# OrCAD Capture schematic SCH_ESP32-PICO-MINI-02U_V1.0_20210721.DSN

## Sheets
1 01_DesignBlock: title: <ESP32-PICO-MINI-02U>; rev: V1.0; note: <01_DesignBlock>
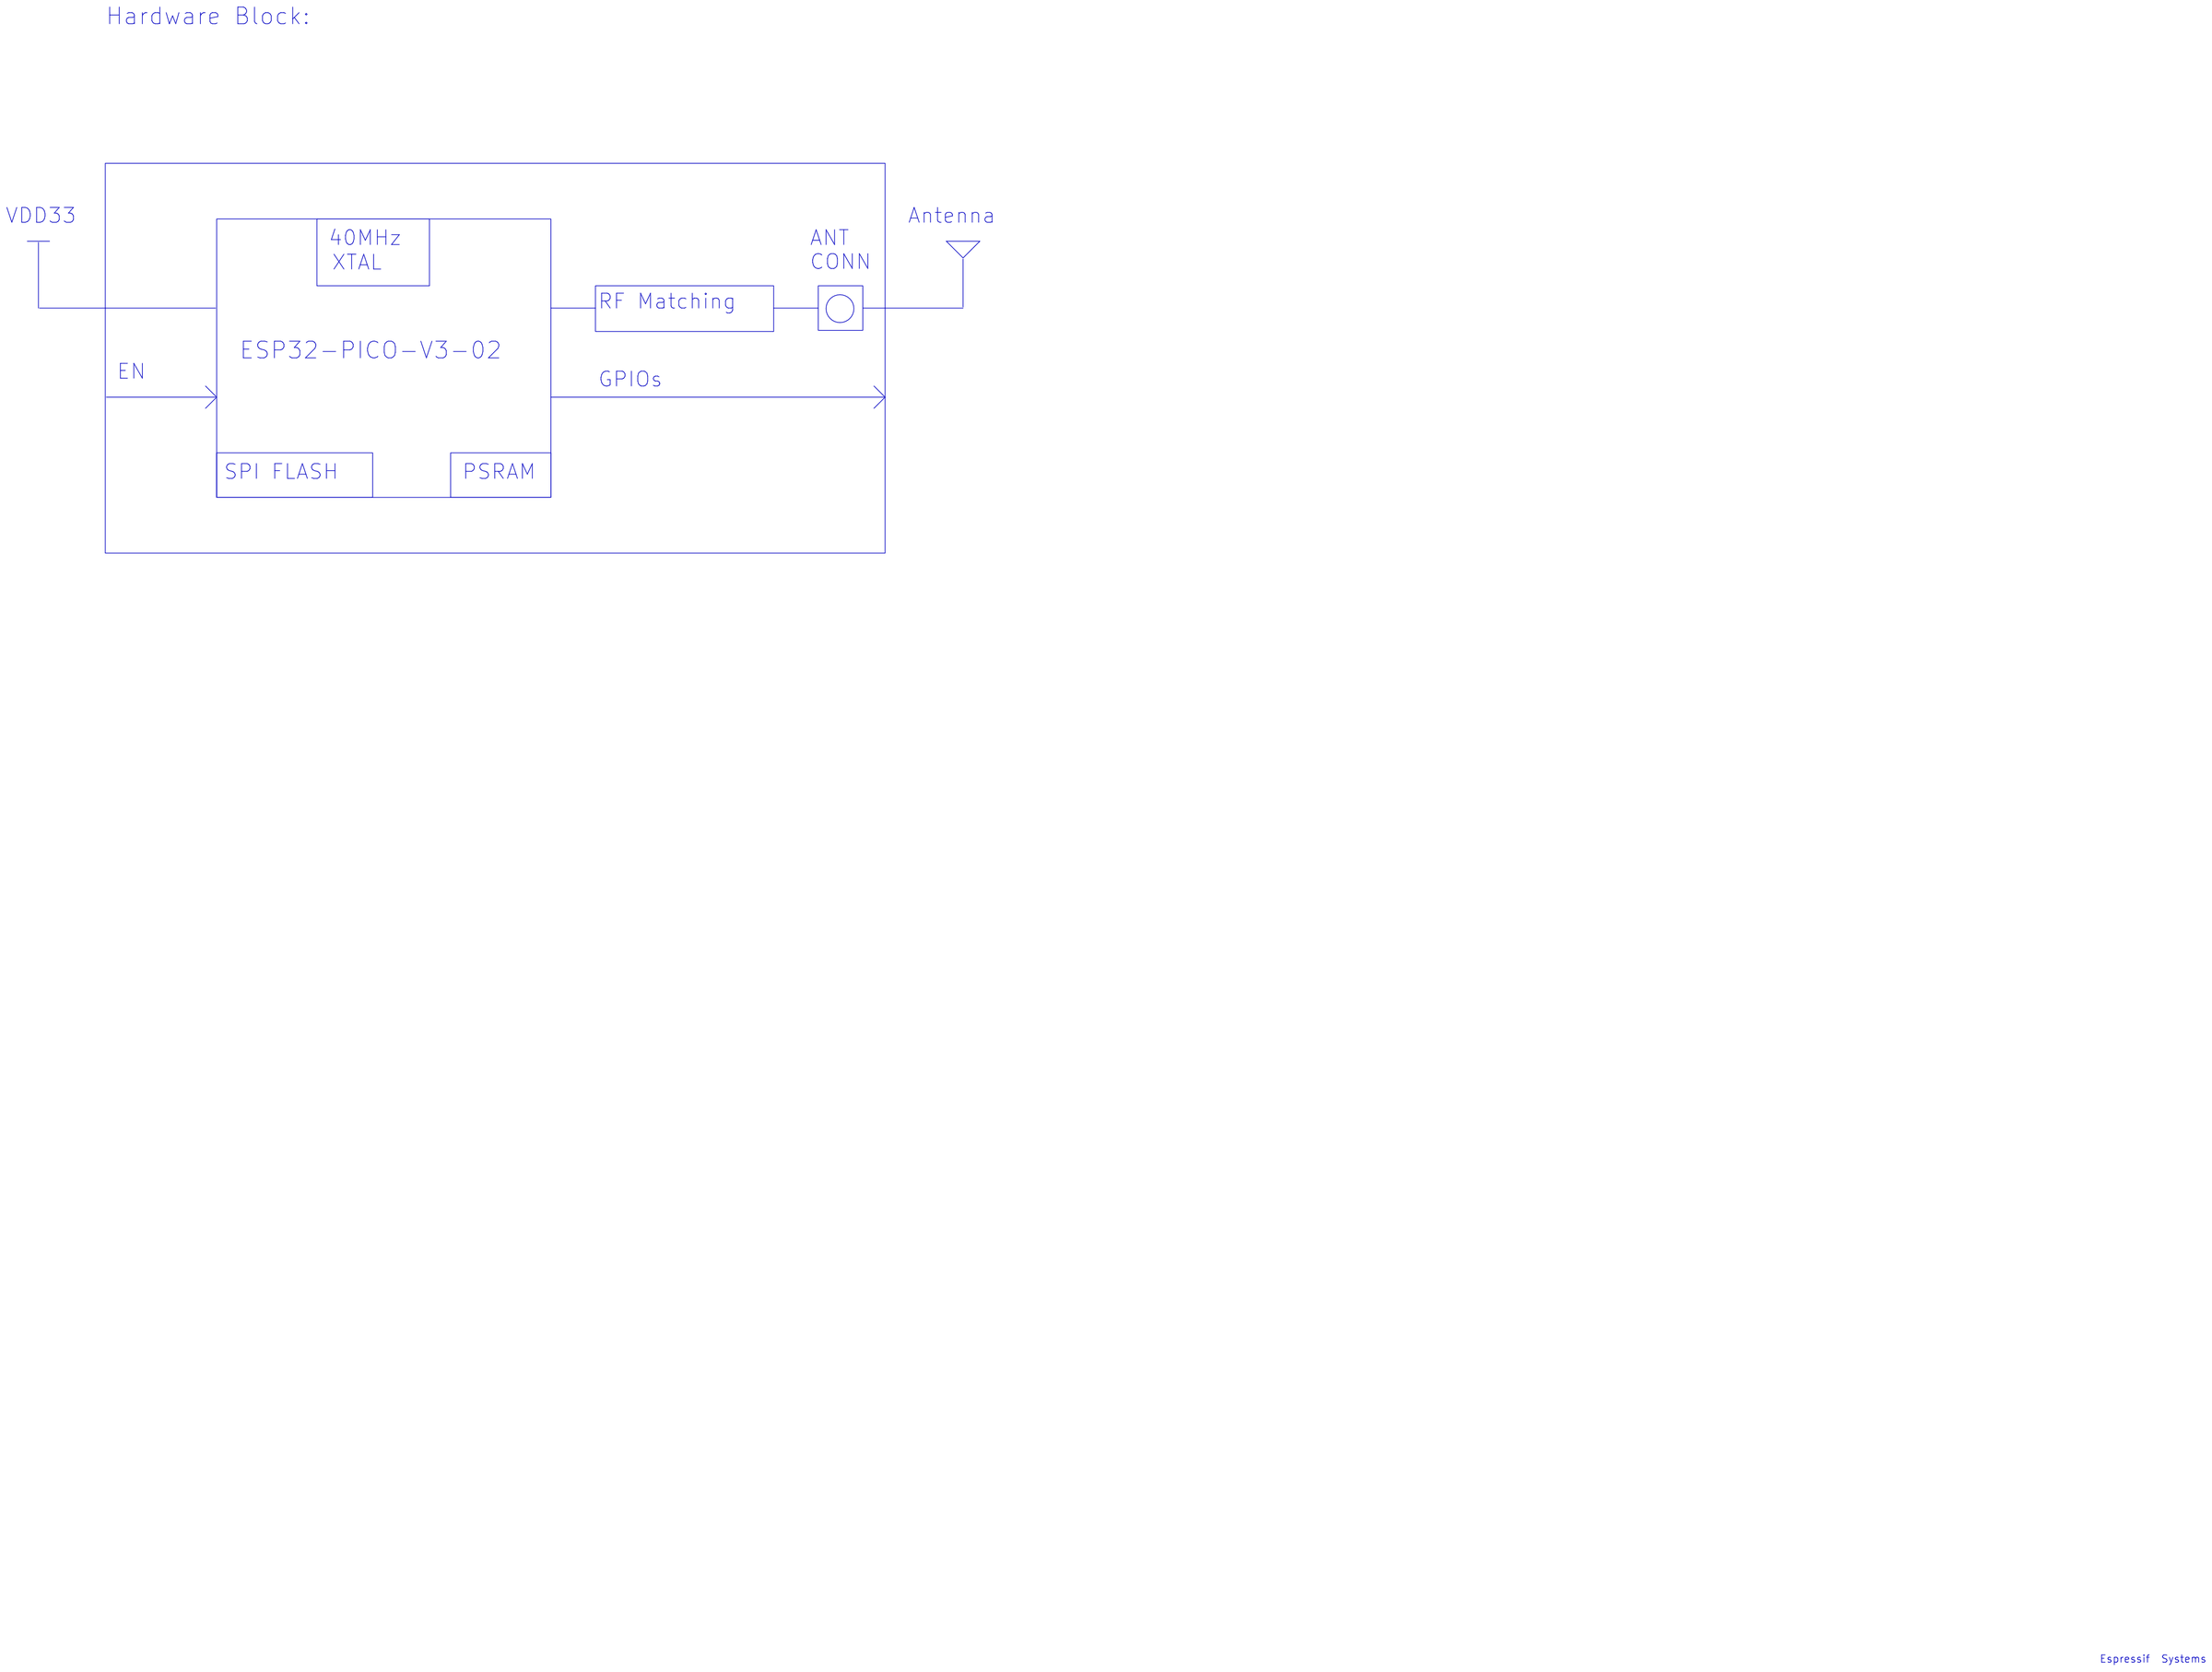
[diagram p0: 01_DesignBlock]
2 02_ESP32-PICO-MINI-02U: size A4; note: <02_ESP32-PICO-MINI-02U>
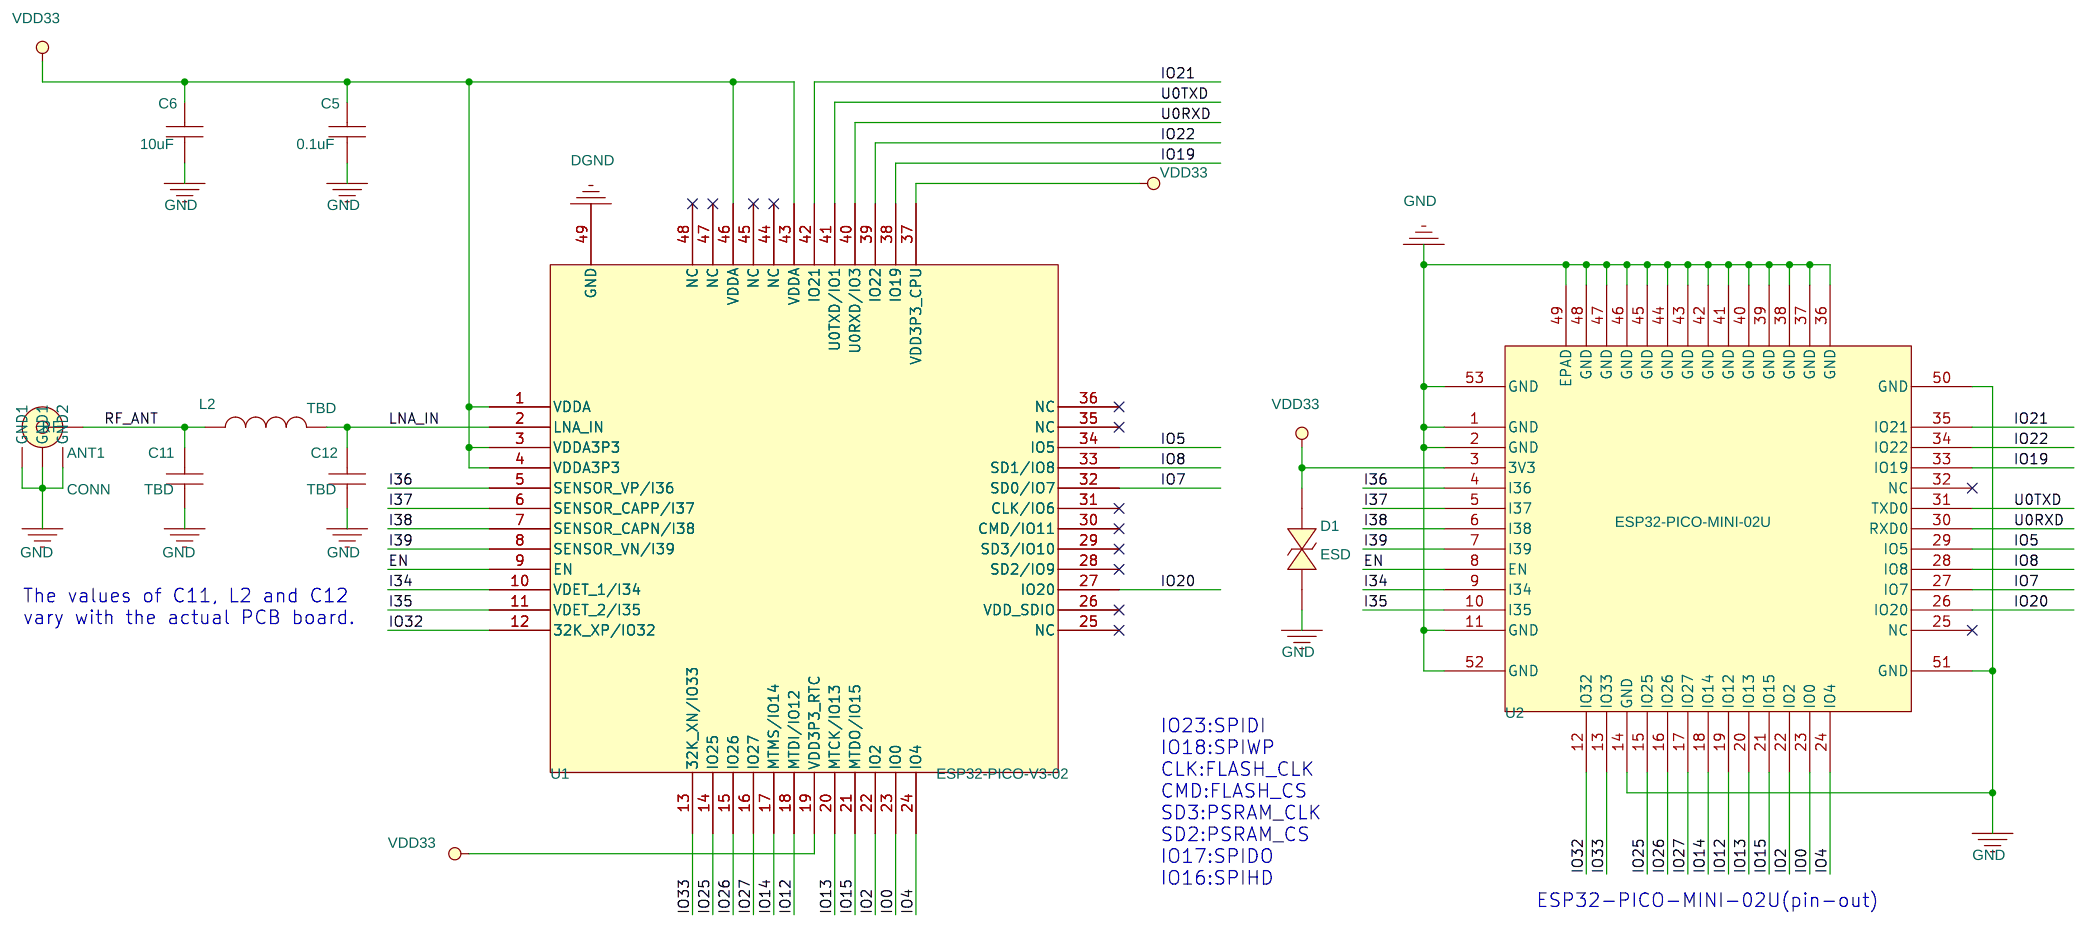
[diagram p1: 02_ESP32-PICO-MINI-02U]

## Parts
ANT1  CONN  [MINI-ANT-TYPED]
C5  0.1uF  [C0201]
C6  10uF  [C0402]
C11  TBD  [C0201]
C12  TBD  [C0201]
D1  ESD  [SOD882]
L2  TBD  [L0201]
U1  ESP32-PICO-V3-02  [QFN48_0P5_7]
U2  ESP32-PICO-MINI-02U  [QFN48_0P8_11P8X9P8]

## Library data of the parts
ANT1 = IPEX_4P
C5 C6 C11 C12 = CAP
D1 = DIODE_BI-DIR_TRIG
L2 = Inductor
U1 = ESP32-PICO-V3-02
U2 = ESP32-PICO-MINI-02

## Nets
GND: ANT1.2(GND2) ANT1.3(GND1) ANT1.4(GND1) C5.2 C6.2 C11.1 C12.1 D1.1 U1.49(GND) U2.1(GND) U2.2(GND) U2.11(GND) U2.14(GND) U2.36(GND) U2.37(GND) U2.38(GND) U2.39(GND) U2.40(GND) U2.41(GND) U2.42(GND) U2.43(GND) U2.44(GND) U2.45(GND) U2.46(GND) U2.47(GND) U2.48(GND) U2.49(EPAD) U2.50(GND) U2.51(GND) U2.52(GND) U2.53(GND)
VDD33: C5.1 C6.1 D1.2 U1.1(VDDA) U1.3(VDDA3P3) U1.4(VDDA3P3) U1.19(VDD3P3_RTC) U1.37(VDD3P3_CPU) U1.43(VDDA) U1.46(VDDA) U2.3(3V3)
EN: U1.9(EN) U2.8(EN)
I34: U1.10(VDET_1/I34) U2.9(I34)
I35: U1.11(VDET_2/I35) U2.10(I35)
I36: U1.5(SENSOR_VP/I36) U2.4(I36)
I37: U1.6(SENSOR_CAPP/I37) U2.5(I37)
I38: U1.7(SENSOR_CAPN/I38) U2.6(I38)
I39: U1.8(SENSOR_VN/I39) U2.7(I39)
IO0: U1.23(IO0) U2.23(IO0)
IO2: U1.22(IO2) U2.22(IO2)
IO4: U1.24(IO4) U2.24(IO4)
IO5: U1.34(IO5) U2.29(IO5)
IO7: U1.32(SD0/IO7) U2.27(IO7)
IO8: U1.33(SD1/IO8) U2.28(IO8)
IO12: U1.18(MTDI/IO12) U2.19(IO12)
IO13: U1.20(MTCK/IO13) U2.20(IO13)
IO14: U1.17(MTMS/IO14) U2.18(IO14)
IO15: U1.21(MTDO/IO15) U2.21(IO15)
IO19: U1.38(IO19) U2.33(IO19)
IO20: U1.27(IO20) U2.26(IO20)
IO21: U1.42(IO21) U2.35(IO21)
IO22: U1.39(IO22) U2.34(IO22)
IO25: U1.14(IO25) U2.15(IO25)
IO26: U1.15(IO26) U2.16(IO26)
IO27: U1.16(IO27) U2.17(IO27)
IO32: U1.12(32K_XP/IO32) U2.12(IO32)
IO33: U1.13(32K_XN/IO33) U2.13(IO33)
LNA_IN: C12.2 L2.1 U1.2(LNA_IN)
RF_ANT: ANT1.1(RF) C11.2 L2.2
U0RXD: U1.40(U0RXD/IO3) U2.30(RXD0)
U0TXD: U1.41(U0TXD/IO1) U2.31(TXD0)

Not connected (* = marked no-connect by the designer): U1 25(NC)* 26(VDD_SDIO)* 28(SD2/IO9)* 29(SD3/IO10)* 30(CMD/IO11)* 31(CLK/IO6)* 35(NC)* 36(NC)* 44(NC)* 45(NC)* 47(NC)* 48(NC)*; U2 25(NC)* 32(NC)*

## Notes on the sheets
sheet 1
- Hardware Block:
- VDD33
- Antenna
- 40MHz
- ANT
  CONN
- XTAL
- RF Matching
- ESP32-PICO-V3-02
- EN
- GPIOs
- SPI FLASH
- PSRAM
- Espressif  Systems
sheet 2
- The values of C11, L2 and C12
  vary with the actual PCB board.
- IO23:SPIDI
  IO18:SPIWP
  CLK:FLASH_CLK
  CMD:FLASH_CS
  SD3:PSRAM_CLK
  SD2:PSRAM_CS
  IO17:SPIDO
  IO16:SPIHD
- ESP32-PICO-MINI-02U(pin-out)
